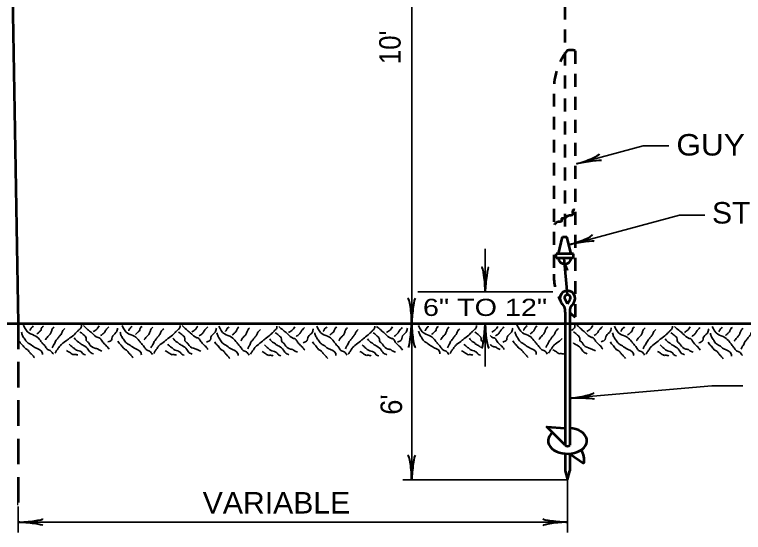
# Model space of a CAD drawing. Extents: x -1 to 679, y 0 to 440.
# Drawn here: x 319.7 to 405.2, y 44.1 to 104.8 of the extents above; entities that cross this region are included whole.
import ezdxf
from ezdxf.enums import TextEntityAlignment as Align

# ---------------------------------------------------------------- set-up
doc = ezdxf.new("R2010")
doc.units = 0
doc.linetypes.add('MEDIUM_DASHED', pattern=[4.5, 3, -1.5])
doc.linetypes.add('SHORT_DASHED', pattern=[2.7, 1.5, -1.2])
doc.layers.add('1', color=7, linetype='Continuous', lineweight=53)

msp = doc.modelspace()

# ---------------------------------------------------------------- linework, layer by layer
at = {"layer": '1', "linetype": 'SHORT_DASHED'}
for p, q in [((384.279, 135.475), (384.279, 78.775)), ((385.499, 100.575), (385.499, 69.335)), ((382.979, 95.535), (382.979, 74.375))]:
    msp.add_line(p, q, dxfattribs=at)
at = {"layer": '1'}
for p, q in [((319.019, 133.035), (320.159, 68.575)), ((383.519, 76.755), (384.019, 78.775)), ((384.019, 78.775), (384.519, 78.775)), ((385.019, 76.755), (384.519, 78.775)), ((385.279, 76.755), (383.259, 76.755)), ((383.259, 76.255), (383.259, 76.755)), ((385.279, 76.255), (383.259, 76.255)), ((384.599, 71.975), (384.219, 76.255)), ((385.279, 76.255), (385.279, 76.755)), ((384.279, 75.555), (384.559, 74.795)), ((384.599, 70.915), (384.299, 71.435)), ((384.599, 70.915), (384.899, 71.435)), ((384.859, 69.915), (384.859, 64.635)), ((295.899, 68.575), (484.219, 68.575)), ((384.859, 64.595), (384.859, 54.315)), ((384.859, 53.315), (384.859, 51.295)), ((384.859, 53.315), (386.499, 52.155))]:
    msp.add_line(p, q, dxfattribs=at)
at = {"layer": '1', "lineweight": 35}
for p, q in [((393.459, 89.415), (385.659, 87.335)), ((393.459, 89.415), (396.479, 89.415)), ((397.719, 81.295), (384.839, 77.835)), ((397.719, 81.295), (400.719, 81.295)), ((374.939, 72.315), (374.939, 77.355)), ((382.859, 72.315), (367.019, 72.315)), ((374.939, 68.575), (374.939, 63.535)), ((401.519, 61.275), (384.859, 59.815)), ((401.519, 61.275), (405.179, 61.275)), ((384.579, 50.235), (365.259, 50.235)), ((384.579, 50.195), (384.579, 44.075)), ((320.159, 47.115), (320.159, 44.075)), ((320.159, 45.275), (384.599, 45.275))]:
    msp.add_line(p, q, dxfattribs=at)
at = {"layer": '1', "linetype": 'MEDIUM_DASHED'}
for p in [(320.159, 68.575), (311.019, 47.415)]:
    msp.add_line(p, (320.159, 47.415), dxfattribs=at)
at = {"layer": '1', "lineweight": 35}
msp.add_lwpolyline([(366.319, 134.955), (366.319, 68.675), (366.319, 50.235)], dxfattribs=at)
at = {"layer": '1'}
for points in [[(384.319, 69.915), (384.319, 64.595), (384.319, 54.315)], [(384.319, 54.315), (382.179, 56.455), (384.319, 56.315)], [(384.319, 53.315), (384.319, 51.295), (384.599, 50.275), (384.859, 51.295)]]:
    msp.add_lwpolyline(points, dxfattribs=at)
at = {"layer": '1', "linetype": 'SHORT_DASHED'}
for centre, radius, start, end in [((390.773, 95.952), 7.798, 143.58388, 183.01714), ((385.002, 99.105), 1.56, 71.15616, 108.84384), ((388.857, 74.159), 5.875, 177.90975, 209.56823), ((388.857, 74.159), 5.875, 227.0576, 235.22035)]:
    msp.add_arc(centre, radius, start, end, dxfattribs=at)
at = {"layer": '1'}
for centre, radius, start, end in [((384.272, 76.323), 0.759, 185.20411, 354.79589), ((384.596, 71.54), 0.894, 337.37581, 202.62419), ((384.595, 71.613), 0.353, 328.9871, 211.0129), ((386.25, 72.446), 2.777, 206.74116, 223.96028), ((383.328, 72.195), 2.319, 313.69833, 334.49446), ((382.852, 70.036), 1.48, 355.24577, 19.00426), ((386.33, 70.036), 1.48, 160.99574, 184.75423), ((384.591, 54.6), 0.387, 227.04039, 312.95961), ((384.451, 52.609), 2.105, 347.48706, 33.42981)]:
    msp.add_arc(centre, radius, start, end, dxfattribs=at)
at = {"layer": '1', "lineweight": 40}
for centre, major_axis, ratio, start_param, end_param in [((386.652, 87.879), (-1.698, -0.618), 0.122415, 0.896353, 3.141593), ((386.808, 87.411), (1.756, 0.287), 0.07063, 6.282307, 8.559703), ((385.82, 78.398), (-1.698, -0.618), 0.122415, 0.896353, 3.141593), ((385.976, 77.931), (1.756, 0.287), 0.07063, 6.282307, 8.559703), ((374.659, 73.416), (0.157, -1.8), 0.122415, 0.896353, 3.141593), ((375.15, 73.445), (0.177, 1.77), 0.07063, 6.282307, 8.559703), ((366.037, 69.768), (0.157, -1.8), 0.122415, 0.896353, 3.141593), ((366.529, 69.798), (0.177, 1.77), 0.07063, 6.282307, 8.559703), ((366.102, 67.539), (-0.177, -1.77), 0.07063, 6.282307, 8.559703), ((366.102, 67.539), (-0.177, -1.77), 0.07063, 6.282307, 8.559703), ((366.594, 67.568), (-0.157, 1.8), 0.122415, 0.896353, 3.141593), ((366.594, 67.568), (-0.157, 1.8), 0.122415, 0.896353, 3.141593), ((374.724, 67.454), (-0.177, -1.77), 0.07063, 6.282307, 8.559703), ((375.216, 67.483), (-0.157, 1.8), 0.122415, 0.896353, 3.141593), ((385.926, 60.188), (-1.779, -0.314), 0.122415, 0.896353, 3.141593), ((385.998, 59.701), (1.779, -0.022), 0.07063, 6.282307, 8.559703), ((366.037, 51.337), (0.157, -1.8), 0.122415, 0.896353, 3.141593), ((366.529, 51.366), (-0.177, -1.77), 0.07063, 3.140715, 5.41811), ((321.255, 45.555), (-1.8, -0.157), 0.122415, 0.896353, 3.141593), ((383.477, 45.49), (-1.77, 0.177), 0.07063, 6.282307, 8.559703), ((321.285, 45.064), (-1.77, 0.177), 0.07063, 3.140715, 5.41811), ((383.506, 44.998), (1.8, 0.157), 0.122415, 0.896353, 3.141593)]:
    msp.add_ellipse(centre, major_axis=major_axis, ratio=ratio, start_param=start_param, end_param=end_param, dxfattribs=at)
at = {"layer": '1'}
msp.add_ellipse((384.591, 54.821), major_axis=(-2.28, 0), ratio=0.663245, start_param=5.582484, end_param=10.879676, dxfattribs=at)
msp.add_spline([(385.439, 81.895), (385.259, 81.895), (385.199, 81.535), (385.159, 81.335), (384.819, 81.255), (384.419, 81.055), (384.259, 80.915), (383.899, 80.875), (383.879, 80.615), (383.539, 80.515), (383.259, 80.415), (383.019, 80.155)], degree=3, dxfattribs=at)
at = {"layer": '1', "lineweight": 35}
for points in [[(378.659, 68.415), (379.319, 67.495), (380.139, 67.115), (380.659, 66.595), (380.919, 66.275), (381.239, 65.895), (381.499, 65.575), (381.899, 65.375), (382.219, 64.995)], [(385.459, 68.415), (385.459, 68.275), (385.399, 68.075), (385.279, 67.955), (385.139, 67.835), (385.119, 67.795)], [(320.539, 67.575), (320.659, 67.175), (320.919, 66.755), (321.239, 66.355), (321.559, 66.155), (322.119, 65.775), (322.979, 65.175), (323.019, 64.935)], [(320.759, 68.375), (321.399, 67.475), (322.239, 67.095), (322.759, 66.575), (323.019, 66.255), (323.339, 65.875), (323.599, 65.555), (323.979, 65.355), (324.299, 64.975)], [(321.919, 68.315), (321.819, 68.175), (321.799, 68.175), (321.739, 68.115), (321.559, 67.835), (321.539, 67.755)], [(323.119, 68.275), (322.919, 68.115), (322.859, 67.955), (322.799, 67.755), (322.659, 67.635), (322.599, 67.575), (322.319, 67.335)], [(324.379, 68.175), (324.179, 67.995), (324.059, 67.675), (323.899, 67.355), (323.539, 66.955), (323.399, 66.755), (323.339, 66.675)], [(325.639, 67.995), (325.339, 67.675), (325.179, 67.315), (324.919, 67.015), (324.719, 66.735), (324.539, 66.515), (324.439, 66.275), (324.299, 66.055), (324.139, 65.735)], [(327.559, 68.375), (327.559, 68.255), (327.499, 68.055), (327.379, 67.935), (327.239, 67.795), (326.979, 67.555), (326.799, 67.355), (326.219, 66.895), (325.879, 66.635), (325.239, 66.135), (324.979, 65.875), (324.859, 65.675), (324.659, 65.415), (324.479, 65.095)], [(327.379, 67.595), (327.559, 67.475), (327.759, 67.315), (328.119, 66.855), (328.139, 66.575), (328.399, 66.355), (328.499, 66.175), (329.139, 65.695), (329.539, 65.575), (329.639, 65.515), (329.979, 65.355)], [(327.799, 68.355), (328.299, 67.895), (328.759, 67.515), (329.539, 66.935), (329.719, 66.875), (329.919, 66.615), (330.239, 66.215), (330.619, 65.835), (330.819, 65.575)], [(328.959, 67.635), (329.399, 67.955), (329.499, 68.095), (329.659, 68.315)], [(329.819, 67.175), (330.179, 67.435), (330.399, 67.755), (330.459, 67.855), (330.599, 67.995), (330.799, 68.215)], [(330.659, 66.435), (331.119, 66.695), (331.179, 66.995), (331.599, 67.515), (331.719, 67.675), (331.799, 67.935), (331.819, 68.055)], [(332.119, 67.555), (332.239, 67.155), (332.499, 66.735), (332.819, 66.315), (333.139, 66.135), (333.699, 65.735), (334.559, 65.155), (334.599, 64.915)], [(332.339, 68.355), (332.979, 67.455), (333.819, 67.075), (334.339, 66.555), (334.599, 66.235), (334.919, 65.855), (335.179, 65.535), (335.559, 65.335), (335.899, 64.955)], [(333.499, 68.295), (333.399, 68.155), (333.379, 68.155), (333.319, 68.095), (333.139, 67.815), (333.119, 67.735)], [(334.699, 68.255), (334.499, 68.095), (334.439, 67.935), (334.379, 67.735), (334.239, 67.615), (334.179, 67.555), (333.899, 67.315)], [(335.959, 68.155), (335.759, 67.975), (335.639, 67.655), (335.479, 67.315), (335.119, 66.935), (334.979, 66.735), (334.919, 66.655)], [(337.219, 67.975), (336.919, 67.655), (336.759, 67.295), (336.499, 66.995), (336.299, 66.715), (336.119, 66.495), (336.019, 66.255), (335.899, 66.035), (335.719, 65.715)], [(339.139, 68.355), (339.139, 68.235), (339.079, 68.035), (338.959, 67.915), (338.819, 67.775), (338.559, 67.535), (338.379, 67.335), (337.799, 66.875), (337.479, 66.615), (336.819, 66.115), (336.559, 65.855), (336.439, 65.655), (336.239, 65.395), (336.059, 65.075)], [(338.959, 67.575), (339.139, 67.455), (339.339, 67.295), (339.699, 66.835), (339.719, 66.555), (339.979, 66.315), (340.079, 66.155), (340.719, 65.675), (341.119, 65.555), (341.219, 65.495), (341.559, 65.335)], [(339.379, 68.335), (339.879, 67.875), (340.339, 67.495), (341.119, 66.915), (341.299, 66.855), (341.499, 66.595), (341.819, 66.195), (342.219, 65.815), (342.399, 65.555)], [(340.539, 67.615), (340.979, 67.935), (341.079, 68.075), (341.239, 68.295)], [(341.399, 67.155), (341.759, 67.415), (341.979, 67.735), (342.039, 67.835), (342.179, 67.975), (342.379, 68.195)], [(342.239, 66.415), (342.699, 66.675), (342.759, 66.975), (343.179, 67.495), (343.299, 67.655), (343.379, 67.895), (343.399, 68.035)], [(343.699, 68.275), (344.339, 67.375), (345.179, 66.995), (345.699, 66.475), (345.959, 66.155), (346.279, 65.775), (346.539, 65.435), (346.919, 65.255), (347.239, 64.855)], [(344.859, 68.215), (344.759, 68.075), (344.719, 68.075), (344.659, 68.015), (344.499, 67.715), (344.459, 67.655)], [(346.039, 68.175), (345.859, 68.015), (345.799, 67.855), (345.719, 67.655), (345.599, 67.535), (345.539, 67.475), (345.239, 67.235)], [(347.299, 68.075), (347.119, 67.895), (346.979, 67.555), (346.819, 67.235), (346.459, 66.855), (346.339, 66.655), (346.279, 66.555)], [(348.559, 67.895), (348.279, 67.555), (348.119, 67.215), (347.859, 66.915), (347.659, 66.635), (347.459, 66.395), (347.379, 66.175), (347.239, 65.955), (347.079, 65.635)], [(350.499, 68.275), (350.499, 68.155), (350.439, 67.955), (350.299, 67.835), (350.179, 67.695), (349.919, 67.435), (349.719, 67.255), (349.139, 66.795), (348.819, 66.535), (348.179, 66.015), (347.919, 65.775), (347.799, 65.575), (347.599, 65.315), (347.399, 64.995)], [(350.719, 68.255), (351.239, 67.795), (351.699, 67.415), (352.459, 66.835), (352.659, 66.775), (352.859, 66.515), (353.179, 66.115), (353.559, 65.735), (353.759, 65.475)], [(351.879, 67.535), (352.339, 67.855), (352.439, 67.975), (352.599, 68.215)], [(352.759, 67.075), (353.119, 67.335), (353.339, 67.655), (353.399, 67.755), (353.539, 67.895), (353.719, 68.115)], [(353.599, 66.335), (354.039, 66.595), (354.119, 66.895), (354.519, 67.395), (354.659, 67.555), (354.719, 67.815), (354.759, 67.955)], [(355.179, 68.275), (355.819, 67.375), (356.659, 66.995), (357.179, 66.475), (357.419, 66.155), (357.759, 65.775), (357.999, 65.435), (358.399, 65.255), (358.719, 64.855)], [(356.339, 68.215), (356.239, 68.075), (356.199, 68.075), (356.139, 68.015), (355.979, 67.715), (355.939, 67.655)], [(357.519, 68.175), (357.339, 68.015), (357.259, 67.855), (357.199, 67.655), (357.079, 67.535), (356.999, 67.475), (356.719, 67.235)], [(358.779, 68.075), (358.579, 67.895), (358.459, 67.555), (358.299, 67.235), (357.939, 66.855), (357.819, 66.655), (357.759, 66.555)], [(360.039, 67.895), (359.759, 67.555), (359.579, 67.215), (359.339, 66.915), (359.139, 66.635), (358.939, 66.395), (358.839, 66.175), (358.719, 65.955), (358.559, 65.635)], [(361.979, 68.275), (361.979, 68.155), (361.919, 67.955), (361.779, 67.835), (361.659, 67.695), (361.399, 67.435), (361.199, 67.255), (360.619, 66.795), (360.299, 66.535), (359.659, 66.015), (359.399, 65.775), (359.259, 65.575), (359.079, 65.315), (358.879, 64.995)], [(362.199, 68.255), (362.719, 67.795), (363.159, 67.415), (363.939, 66.835), (364.139, 66.775), (364.319, 66.515), (364.659, 66.115), (365.039, 65.735), (365.239, 65.475)], [(363.359, 67.535), (363.819, 67.855), (363.919, 67.975), (364.079, 68.215)], [(364.239, 67.075), (364.579, 67.335), (364.819, 67.655), (364.879, 67.755), (364.999, 67.895), (365.199, 68.115)], [(364.659, 66.415), (365.099, 66.675), (365.179, 66.975), (365.599, 67.495), (365.719, 67.655), (365.779, 67.895), (365.819, 68.035)], [(367.099, 68.355), (367.759, 67.455), (368.579, 67.075), (369.099, 66.555), (369.359, 66.235), (369.679, 65.855), (369.939, 65.535), (370.339, 65.335), (370.659, 64.955)], [(367.119, 67.675), (367.259, 67.295), (367.519, 66.875), (367.839, 66.455), (368.159, 66.255), (368.699, 65.875), (369.579, 65.295), (369.619, 65.035)], [(368.259, 68.295), (368.179, 68.155), (368.139, 68.155), (368.079, 68.095), (367.919, 67.815), (367.879, 67.735)], [(369.459, 68.255), (369.259, 68.095), (369.199, 67.935), (369.139, 67.735), (368.999, 67.615), (368.939, 67.555), (368.659, 67.315)], [(370.719, 68.155), (370.519, 67.975), (370.399, 67.655), (370.239, 67.315), (369.879, 66.935), (369.759, 66.735), (369.679, 66.655)], [(371.979, 67.975), (371.679, 67.655), (371.519, 67.295), (371.259, 66.995), (371.079, 66.715), (370.879, 66.495), (370.779, 66.255), (370.659, 66.035), (370.499, 65.715)], [(373.899, 68.355), (373.899, 68.235), (373.839, 68.035), (373.719, 67.915), (373.579, 67.775), (373.319, 67.535), (373.139, 67.335), (372.559, 66.875), (372.239, 66.615), (371.579, 66.115), (371.339, 65.855), (371.199, 65.655), (370.999, 65.395), (370.819, 65.075)], [(373.719, 67.575), (373.899, 67.455), (374.099, 67.295), (374.459, 66.835), (374.499, 66.555), (374.659, 66.395)], [(375.719, 67.575), (376.159, 67.895), (376.259, 68.015), (376.419, 68.255)], [(376.159, 67.155), (376.519, 67.415), (376.739, 67.735), (376.819, 67.835), (376.939, 67.975), (377.139, 68.195)], [(376.999, 66.415), (377.459, 66.675), (377.519, 66.975), (377.939, 67.495), (378.059, 67.655), (378.139, 67.895), (378.159, 68.035)], [(378.439, 67.595), (378.559, 67.195), (378.819, 66.795), (379.139, 66.375), (379.479, 66.175), (380.019, 65.795), (380.899, 65.215), (380.919, 64.955)], [(379.819, 68.335), (379.719, 68.195), (379.699, 68.195), (379.639, 68.135), (379.479, 67.855), (379.439, 67.795)], [(381.019, 68.295), (380.819, 68.135), (380.759, 67.975), (380.699, 67.795), (380.559, 67.655), (380.499, 67.595), (380.219, 67.375)], [(382.279, 68.195), (382.079, 68.015), (381.959, 67.695), (381.799, 67.375), (381.439, 66.975), (381.299, 66.795), (381.239, 66.695)], [(383.539, 68.015), (383.239, 67.695), (383.079, 67.335), (382.819, 67.035), (382.639, 66.755), (382.439, 66.535), (382.339, 66.295), (382.219, 66.075), (382.059, 65.755)], [(385.279, 67.615), (385.459, 67.495), (385.659, 67.335), (386.019, 66.875), (386.039, 66.595), (386.299, 66.375), (386.399, 66.215), (387.039, 65.715), (387.439, 65.595), (387.539, 65.535), (387.879, 65.375)], [(385.699, 68.375), (386.219, 67.915), (386.659, 67.535), (387.439, 66.955), (387.619, 66.895), (387.819, 66.635), (388.139, 66.255), (388.539, 65.855), (388.719, 65.595)], [(386.859, 67.655), (387.299, 67.975), (387.399, 68.115), (387.559, 68.335)], [(387.719, 67.195), (388.079, 67.455), (388.299, 67.795), (388.379, 67.875), (388.499, 68.015), (388.699, 68.235)], [(388.559, 66.455), (389.019, 66.715), (389.079, 67.015), (389.499, 67.535), (389.619, 67.695), (389.699, 67.955), (389.719, 68.075)], [(390.099, 68.275), (390.739, 67.375), (391.579, 66.995), (392.099, 66.475), (392.359, 66.155), (392.679, 65.775), (392.939, 65.435), (393.319, 65.255), (393.639, 64.855)], [(391.259, 68.215), (391.159, 68.075), (391.139, 68.075), (391.059, 68.015), (390.899, 67.715), (390.879, 67.655)], [(392.459, 68.175), (392.259, 68.015), (392.199, 67.855), (392.139, 67.655), (391.999, 67.535), (391.939, 67.475), (391.639, 67.235)], [(393.719, 68.075), (393.519, 67.895), (393.379, 67.555), (393.219, 67.235), (392.879, 66.855), (392.739, 66.655), (392.679, 66.555)], [(394.959, 67.895), (394.679, 67.555), (394.519, 67.215), (394.259, 66.915), (394.059, 66.635), (393.879, 66.395), (393.779, 66.175), (393.639, 65.955), (393.479, 65.635)], [(396.899, 68.275), (396.899, 68.155), (396.839, 67.955), (396.719, 67.835), (396.579, 67.695), (396.319, 67.435), (396.139, 67.255), (395.559, 66.795), (395.219, 66.535), (394.579, 66.015), (394.319, 65.775), (394.199, 65.575), (393.999, 65.315), (393.799, 64.995)], [(397.139, 68.255), (397.639, 67.795), (398.099, 67.415), (398.879, 66.835), (399.059, 66.775), (399.259, 66.515), (399.579, 66.115), (399.959, 65.735), (400.159, 65.475)], [(398.299, 67.535), (398.739, 67.855), (398.839, 67.975), (398.999, 68.215)], [(399.159, 67.075), (399.519, 67.335), (399.739, 67.655), (399.799, 67.755), (399.939, 67.895), (400.119, 68.115)], [(399.999, 66.335), (400.459, 66.595), (400.519, 66.895), (400.939, 67.395), (401.059, 67.555), (401.119, 67.815), (401.159, 67.955)], [(401.579, 68.235), (402.219, 67.335), (403.059, 66.955), (403.579, 66.435), (403.839, 66.115), (404.159, 65.715), (404.419, 65.395), (404.799, 65.215), (405.119, 64.815)], [(402.739, 68.175), (402.639, 68.035), (402.599, 68.035), (402.539, 67.975), (402.379, 67.675), (402.359, 67.615)], [(403.939, 68.135), (403.739, 67.975), (403.679, 67.815), (403.599, 67.615), (403.479, 67.495), (403.419, 67.435), (403.119, 67.195)], [(405.179, 68.035), (404.999, 67.835), (404.859, 67.515), (404.699, 67.195), (404.359, 66.815), (404.219, 66.615), (404.159, 66.515)], [(406.439, 67.835), (406.159, 67.515), (405.999, 67.175), (405.739, 66.875), (405.539, 66.595), (405.339, 66.355), (405.259, 66.135), (405.119, 65.915), (404.959, 65.595)], [(326.719, 66.895), (327.219, 66.415), (327.299, 66.375), (327.399, 66.275), (327.819, 66.015), (328.339, 65.575), (328.499, 65.315), (328.979, 65.015)], [(338.299, 66.875), (338.799, 66.395), (338.879, 66.355), (338.979, 66.255), (339.399, 65.995), (339.919, 65.555), (340.079, 65.295), (340.559, 64.995)], [(343.459, 67.475), (343.599, 67.075), (343.859, 66.655), (344.179, 66.235), (344.499, 66.055), (345.039, 65.655), (345.919, 65.075), (345.959, 64.815)], [(349.659, 66.795), (350.139, 66.315), (350.239, 66.275), (350.339, 66.175), (350.759, 65.915), (351.279, 65.475), (351.439, 65.215), (351.919, 64.915)], [(350.299, 67.495), (350.499, 67.375), (350.699, 67.215), (351.039, 66.755), (351.079, 66.475), (351.339, 66.235), (351.439, 66.075), (352.079, 65.595), (352.459, 65.475), (352.559, 65.395), (352.919, 65.235)], [(354.939, 67.475), (355.079, 67.075), (355.339, 66.655), (355.659, 66.235), (355.979, 66.055), (356.519, 65.655), (357.399, 65.075), (357.419, 64.815)], [(361.139, 66.795), (361.619, 66.315), (361.719, 66.275), (361.819, 66.175), (362.239, 65.915), (362.739, 65.475), (362.919, 65.215), (363.399, 64.915)], [(361.779, 67.495), (361.979, 67.375), (362.159, 67.215), (362.519, 66.755), (362.559, 66.475), (362.819, 66.235), (362.919, 66.075), (363.559, 65.595), (363.939, 65.475), (364.039, 65.395), (364.399, 65.235)], [(373.079, 66.875), (373.559, 66.395), (373.659, 66.355), (373.739, 66.255), (374.159, 65.995), (374.419, 65.775)], [(375.519, 67.195), (375.879, 66.915), (376.079, 66.855), (376.259, 66.595), (376.579, 66.195), (376.979, 65.815), (377.159, 65.555)], [(383.979, 66.815), (383.799, 66.655), (383.139, 66.155), (382.879, 65.895), (382.759, 65.695), (382.559, 65.435), (382.379, 65.115)], [(389.879, 67.475), (389.999, 67.075), (390.259, 66.655), (390.579, 66.235), (390.899, 66.055), (391.459, 65.655), (392.319, 65.075), (392.359, 64.815)], [(396.059, 66.795), (396.539, 66.315), (396.639, 66.275), (396.739, 66.175), (397.159, 65.915), (397.679, 65.475), (397.839, 65.215), (398.319, 64.915)], [(396.719, 67.495), (396.899, 67.375), (397.099, 67.215), (397.459, 66.755), (397.479, 66.475), (397.739, 66.235), (397.839, 66.075), (398.479, 65.595), (398.879, 65.475), (398.959, 65.395), (399.319, 65.235)], [(401.359, 67.435), (401.479, 67.035), (401.739, 66.615), (402.059, 66.195), (402.379, 66.015), (402.939, 65.615), (403.799, 65.035), (403.839, 64.775)], [(320.279, 66.535), (320.399, 66.315), (320.659, 66.055), (320.979, 65.675), (321.279, 65.475), (321.539, 65.155), (321.799, 64.895), (322.059, 64.575)], [(326.119, 66.175), (326.539, 65.795), (326.699, 65.675), (326.979, 65.475), (327.559, 65.255), (327.759, 65.015), (328.059, 64.895)], [(331.859, 66.515), (331.979, 66.295), (332.239, 66.035), (332.559, 65.655), (332.859, 65.455), (333.119, 65.135), (333.379, 64.875), (333.639, 64.555)], [(337.699, 66.155), (338.119, 65.775), (338.279, 65.655), (338.559, 65.455), (339.139, 65.235), (339.339, 64.995), (339.639, 64.875)], [(343.219, 66.435), (343.339, 66.215), (343.599, 65.955), (343.919, 65.555), (344.219, 65.375), (344.459, 65.055), (344.719, 64.795), (344.979, 64.475)], [(349.039, 66.075), (349.459, 65.695), (349.619, 65.555), (349.919, 65.375), (350.499, 65.155), (350.699, 64.915), (350.979, 64.795)], [(354.679, 66.435), (354.819, 66.215), (355.079, 65.955), (355.399, 65.555), (355.679, 65.375), (355.939, 65.055), (356.199, 64.795), (356.459, 64.475)], [(360.519, 66.075), (360.939, 65.695), (361.099, 65.555), (361.399, 65.375), (361.979, 65.155), (362.159, 64.915), (362.459, 64.795)], [(372.459, 66.155), (372.879, 65.775), (373.039, 65.655), (373.319, 65.455), (373.899, 65.235), (374.099, 64.995), (374.399, 64.875)], [(375.519, 66.135), (375.859, 65.895), (376.259, 65.755), (376.339, 65.695), (376.699, 65.535)], [(378.179, 66.555), (378.319, 66.335), (378.559, 66.075), (378.899, 65.695), (379.179, 65.495), (379.439, 65.175), (379.699, 64.915), (379.959, 64.595)], [(385.279, 66.315), (385.299, 66.295), (385.719, 66.035), (386.239, 65.595), (386.399, 65.335), (386.879, 65.035)], [(389.619, 66.435), (389.739, 66.215), (389.999, 65.955), (390.319, 65.555), (390.619, 65.375), (390.879, 65.055), (391.139, 64.795), (391.399, 64.475)], [(395.459, 66.075), (395.879, 65.695), (396.039, 65.555), (396.319, 65.375), (396.899, 65.155), (397.099, 64.915), (397.379, 64.795)], [(401.099, 66.395), (401.219, 66.175), (401.479, 65.915), (401.799, 65.515), (402.099, 65.335), (402.359, 65.015), (402.599, 64.755), (402.859, 64.435)], [(325.819, 65.415), (326.059, 65.275), (326.479, 64.995), (326.539, 64.955), (326.719, 64.955), (327.139, 64.895)], [(337.399, 65.395), (337.639, 65.255), (338.059, 64.975), (338.119, 64.935), (338.299, 64.935), (338.719, 64.875)], [(348.759, 65.315), (348.979, 65.175), (349.399, 64.895), (349.459, 64.855), (349.659, 64.855), (350.079, 64.795)], [(360.239, 65.315), (360.459, 65.175), (360.879, 64.895), (360.939, 64.855), (361.139, 64.855), (361.559, 64.795)], [(372.159, 65.395), (372.399, 65.255), (372.819, 64.975), (372.879, 64.935), (373.079, 64.935), (373.499, 64.875)], [(382.859, 65.515), (383.079, 65.395), (383.499, 65.095), (383.559, 65.055), (383.759, 65.055), (384.179, 64.995)], [(395.159, 65.315), (395.379, 65.175), (395.799, 64.895), (395.879, 64.855), (396.059, 64.855), (396.479, 64.795)]]:
    msp.add_spline(points, degree=3, dxfattribs=at)

# ---------------------------------------------------------------- texts
at = {"layer": '1'}
for s, width, p in [("10'", 0.9, (365.019, 100.989)), ("6'", 0.95, (365.179, 59.075))]:
    msp.add_text(s, height=2.52, rotation=90, dxfattribs=dict(at, width=width)).set_placement(p, align=Align.CENTER)
for s, height, width, p in [('GUY GUARD', 2.52, 1.1, (408.591, 88.295)), ('6" TO 12"', 2.016, 1.25, (374.917, 69.475)), ('VARIABLE', 2.52, 1.05, (350.451, 46.295))]:
    msp.add_text(s, height=height, dxfattribs=dict(at, width=width)).set_placement(p, align=Align.CENTER)
at = {"layer": '1', "width": 1.05}
msp.add_text('STRANVISE', height=2.52, dxfattribs=at).set_placement((401.539, 80.315))

doc.saveas('drawing.dxf')
